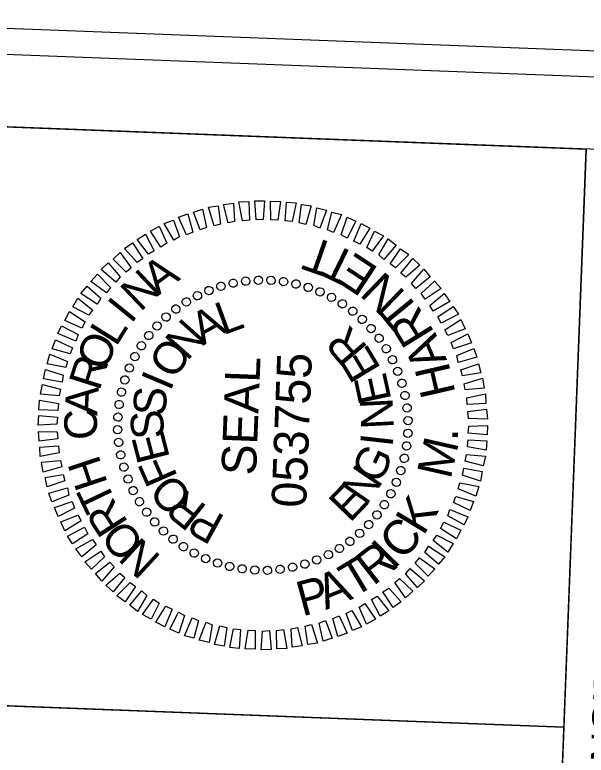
# Model space of a CAD drawing. Extents: x 2097096 to 2098260, y 686401 to 688363.
# Drawn here: x 2097223.6 to 2097322.3, y 688066.3 to 688194.3 of the extents above; entities that cross this region are included whole.
import ezdxf

# ---------------------------------------------------------------- set-up
doc = ezdxf.new("R2010")
doc.units = 0
for name, color, linetype in [('Sheet PE Seal Cell', 7, 'Continuous'), ('Sheet Plot Border Inside CELL', 7, 'Continuous'), ('Sheet Plot Border Outside CELL', 7, 'Continuous'), ('Sheet Profile CELL', 7, 'Continuous'), ('Sheet Sticker Exception Certification CELL', 7, 'Continuous')]:
    doc.layers.add(name, color=color, linetype=linetype)

msp = doc.modelspace()

# ---------------------------------------------------------------- linework, layer by layer
at = {"layer": 'Sheet PE Seal Cell'}
for p, q in [((2097261.29, 688147.95), (2097261.29, 688147.95)), ((2097263.5, 688148.27), (2097263.5, 688148.27)), ((2097265.66, 688148.49), (2097265.66, 688148.49)), ((2097267.86, 688148.45), (2097267.86, 688148.45)), ((2097270.05, 688148.22), (2097270.05, 688148.22)), ((2097272.19, 688147.78), (2097272.19, 688147.78)), ((2097257.13, 688146.71), (2097257.13, 688146.71)), ((2097259.16, 688147.43), (2097259.16, 688147.43)), ((2097274.27, 688147.25), (2097274.27, 688147.25)), ((2097276.34, 688146.47), (2097276.34, 688146.47)), ((2097255.15, 688145.79), (2097255.15, 688145.79)), ((2097278.3, 688145.5), (2097278.3, 688145.5)), ((2097253.21, 688144.71), (2097253.21, 688144.71)), ((2097280.21, 688144.42), (2097280.21, 688144.42)), ((2097251.41, 688143.53), (2097251.41, 688143.53)), ((2097281.96, 688143.11), (2097281.96, 688143.11)), ((2097249.7, 688142.09), (2097249.7, 688142.09)), ((2097283.66, 688141.69), (2097283.66, 688141.69)), ((2097248.14, 688140.6), (2097248.14, 688140.6)), ((2097285.15, 688140.13), (2097285.15, 688140.13)), ((2097246.73, 688138.9), (2097246.73, 688138.9)), ((2097286.59, 688138.43), (2097286.59, 688138.43)), ((2097245.41, 688137.15), (2097245.41, 688137.15)), ((2097287.77, 688136.63), (2097287.77, 688136.63)), ((2097244.34, 688135.24), (2097244.34, 688135.24)), ((2097288.85, 688134.69), (2097288.85, 688134.69)), ((2097243.36, 688133.28), (2097243.36, 688133.28)), ((2097289.77, 688132.7), (2097289.77, 688132.7)), ((2097242.58, 688131.21), (2097242.58, 688131.21)), ((2097290.49, 688130.67), (2097290.49, 688130.67)), ((2097242.05, 688129.13), (2097242.05, 688129.13)), ((2097291.01, 688128.55), (2097291.01, 688128.55)), ((2097241.62, 688126.99), (2097241.62, 688126.99)), ((2097291.33, 688126.34), (2097291.33, 688126.34)), ((2097241.38, 688124.8), (2097241.38, 688124.8)), ((2097266.45, 688123.39), (2097266.45, 688123.39)), ((2097291.55, 688124.18), (2097291.55, 688124.18)), ((2097241.35, 688122.6), (2097241.35, 688122.6)), ((2097291.51, 688121.97), (2097291.51, 688121.97)), ((2097241.57, 688120.44), (2097241.57, 688120.44)), ((2097291.28, 688119.78), (2097291.28, 688119.78)), ((2097241.88, 688118.22), (2097241.88, 688118.22)), ((2097290.85, 688117.65), (2097290.85, 688117.65)), ((2097242.4, 688116.1), (2097242.4, 688116.1)), ((2097290.32, 688115.57), (2097290.32, 688115.57)), ((2097243.12, 688114.07), (2097243.12, 688114.07)), ((2097289.54, 688113.49), (2097289.54, 688113.49)), ((2097244.05, 688112.09), (2097244.05, 688112.09)), ((2097288.56, 688111.53), (2097288.56, 688111.53)), ((2097245.12, 688110.14), (2097245.12, 688110.14)), ((2097287.49, 688109.62), (2097287.49, 688109.62)), ((2097246.31, 688108.35), (2097246.31, 688108.35)), ((2097286.17, 688107.87), (2097286.17, 688107.87)), ((2097247.74, 688106.64), (2097247.74, 688106.64)), ((2097284.75, 688106.17), (2097284.75, 688106.17)), ((2097249.23, 688105.08), (2097249.23, 688105.08)), ((2097283.19, 688104.68), (2097283.19, 688104.68)), ((2097250.93, 688103.67), (2097250.93, 688103.67)), ((2097281.49, 688103.25), (2097281.49, 688103.25)), ((2097252.68, 688102.35), (2097252.68, 688102.35)), ((2097279.69, 688102.06), (2097279.69, 688102.06)), ((2097254.59, 688101.27), (2097254.59, 688101.27)), ((2097277.75, 688100.99), (2097277.75, 688100.99)), ((2097256.56, 688100.3), (2097256.56, 688100.3)), ((2097258.63, 688099.52), (2097258.63, 688099.52)), ((2097273.73, 688099.34), (2097273.73, 688099.34)), ((2097275.76, 688100.06), (2097275.76, 688100.06)), ((2097260.71, 688098.99), (2097260.71, 688098.99)), ((2097262.84, 688098.56), (2097262.84, 688098.56)), ((2097265.04, 688098.32), (2097265.04, 688098.32)), ((2097267.24, 688098.29), (2097267.24, 688098.29)), ((2097269.4, 688098.51), (2097269.4, 688098.51)), ((2097271.61, 688098.82), (2097271.61, 688098.82))]:
    msp.add_line(p, q, dxfattribs=at)
for points in [[(2097260.48, 688158.34), (2097259.65, 688161.52), (2097261.36, 688161.76), (2097261.54, 688158.6)], [(2097262.9, 688158.7), (2097262.32, 688161.97), (2097264.03, 688162.06), (2097264.11, 688158.85)], [(2097265.31, 688158.91), (2097265.03, 688162.17), (2097266.74, 688162.2), (2097266.51, 688158.96)], [(2097267.81, 688158.86), (2097267.78, 688162.11), (2097269.48, 688162.05), (2097269.01, 688158.81)], [(2097270.3, 688158.71), (2097270.53, 688161.96), (2097272.17, 688161.8), (2097271.5, 688158.57)], [(2097255.63, 688157.13), (2097254.45, 688160.22), (2097256.02, 688160.71), (2097256.7, 688157.59)], [(2097258.06, 688157.83), (2097257.04, 688161.07), (2097258.7, 688161.31), (2097259.12, 688158.14)], [(2097272.69, 688158.37), (2097273.12, 688161.56), (2097274.81, 688161.29), (2097273.88, 688158.08)], [(2097275.23, 688157.88), (2097275.74, 688160.96), (2097277.43, 688160.54), (2097276.26, 688157.44)], [(2097253.25, 688156.32), (2097251.86, 688159.32), (2097253.49, 688159.91), (2097254.37, 688156.77)], [(2097277.6, 688157.13), (2097278.37, 688160.21), (2097280, 688159.79), (2097278.63, 688156.69)], [(2097279.97, 688156.29), (2097280.99, 688159.36), (2097282.51, 688158.65), (2097281, 688155.7)], [(2097251.06, 688155.4), (2097249.42, 688158.26), (2097251, 688158.85), (2097252.04, 688155.96)], [(2097282.13, 688155.21), (2097283.4, 688158.26), (2097284.92, 688157.45), (2097283.21, 688154.67)], [(2097248.81, 688154.18), (2097247.02, 688156.91), (2097248.55, 688157.8), (2097249.84, 688154.85)], [(2097284.39, 688154.12), (2097285.75, 688156.92), (2097287.27, 688156.11), (2097285.31, 688153.49)], [(2097246.72, 688152.96), (2097244.71, 688155.49), (2097246.2, 688156.39), (2097247.69, 688153.53)], [(2097286.49, 688152.84), (2097288.1, 688155.58), (2097289.46, 688154.53), (2097287.36, 688152.01)], [(2097244.71, 688151.54), (2097242.55, 688153.92), (2097243.94, 688154.92), (2097245.74, 688152.2)], [(2097242.84, 688149.86), (2097240.58, 688152.1), (2097241.82, 688153.25), (2097243.67, 688150.58)], [(2097288.43, 688151.26), (2097290.23, 688153.9), (2097291.65, 688152.89), (2097289.36, 688150.58)], [(2097290.27, 688149.69), (2097292.32, 688152.22), (2097293.58, 688151.07), (2097291.15, 688148.96)], [(2097241.03, 688148.13), (2097238.51, 688150.28), (2097239.75, 688151.43), (2097241.81, 688149.05)], [(2097292.1, 688147.87), (2097294.25, 688150.34), (2097295.35, 688149.05), (2097292.87, 688147.04)], [(2097239.41, 688146.29), (2097236.73, 688148.24), (2097237.88, 688149.5), (2097240.14, 688147.21)], [(2097293.79, 688146.16), (2097296.07, 688148.27), (2097297.23, 688147.02), (2097294.45, 688145.18)], [(2097237.83, 688144.3), (2097235, 688146.16), (2097236.1, 688147.42), (2097238.47, 688145.37)], [(2097236.4, 688142.4), (2097233.61, 688143.86), (2097234.51, 688145.33), (2097237.04, 688143.33)], [(2097295.26, 688144.1), (2097297.74, 688146.15), (2097298.74, 688144.76), (2097295.88, 688143.12)], [(2097296.69, 688142.14), (2097299.31, 688143.89), (2097300.21, 688142.56), (2097297.25, 688141.02)], [(2097235.17, 688140.15), (2097232.27, 688141.51), (2097233.03, 688143.03), (2097235.76, 688141.23)], [(2097297.85, 688139.9), (2097300.62, 688141.64), (2097301.36, 688140.06), (2097298.42, 688138.92)], [(2097234.13, 688137.94), (2097231.03, 688139.21), (2097231.68, 688140.58), (2097234.53, 688139.07)], [(2097298.97, 688137.7), (2097301.83, 688139.19), (2097302.47, 688137.62), (2097299.38, 688136.58)], [(2097233.15, 688135.72), (2097230.08, 688136.59), (2097230.64, 688138.12), (2097233.54, 688136.76)], [(2097299.93, 688135.46), (2097302.88, 688136.65), (2097303.42, 688135.13), (2097300.19, 688134.2)], [(2097232.4, 688133.35), (2097229.18, 688133.97), (2097229.64, 688135.66), (2097232.69, 688134.39)], [(2097300.64, 688132.98), (2097303.68, 688134.02), (2097304.07, 688132.45), (2097300.95, 688131.92)], [(2097231.76, 688130.82), (2097228.58, 688131.39), (2097228.89, 688133.03), (2097231.95, 688132.01)], [(2097301.2, 688130.56), (2097304.39, 688131.49), (2097304.67, 688129.78), (2097301.41, 688129.5)], [(2097231.27, 688128.44), (2097228.03, 688128.76), (2097228.39, 688130.4), (2097231.51, 688129.63)], [(2097301.66, 688128.14), (2097304.88, 688128.82), (2097304.97, 688127.16), (2097301.76, 688126.94)], [(2097231.02, 688125.95), (2097227.77, 688126.07), (2097227.89, 688127.72), (2097231.12, 688127.14)], [(2097301.86, 688125.73), (2097305.08, 688126.16), (2097305.22, 688124.45), (2097301.97, 688124.53)], [(2097230.88, 688123.55), (2097227.62, 688123.42), (2097227.73, 688125.07), (2097230.97, 688124.75)], [(2097231.03, 688121.04), (2097227.81, 688120.62), (2097227.68, 688122.32), (2097230.93, 688122.25)], [(2097302.02, 688123.22), (2097305.27, 688123.35), (2097305.16, 688121.7), (2097301.92, 688122.03)], [(2097301.88, 688120.83), (2097305.12, 688120.7), (2097305.01, 688119.06), (2097301.78, 688119.63)], [(2097231.24, 688118.63), (2097228.01, 688117.96), (2097227.92, 688119.61), (2097231.14, 688119.84)], [(2097301.63, 688118.33), (2097304.87, 688118.01), (2097304.51, 688116.37), (2097301.38, 688117.14)], [(2097231.7, 688116.21), (2097228.51, 688115.28), (2097228.22, 688117), (2097231.49, 688117.27)], [(2097301.14, 688115.95), (2097304.32, 688115.38), (2097304.01, 688113.74), (2097300.94, 688114.76)], [(2097232.25, 688113.79), (2097229.21, 688112.76), (2097228.82, 688114.32), (2097231.95, 688114.85)], [(2097300.49, 688113.42), (2097303.72, 688112.8), (2097303.25, 688111.12), (2097300.2, 688112.38)], [(2097232.96, 688111.31), (2097230.01, 688110.12), (2097229.47, 688111.64), (2097232.71, 688112.57)], [(2097299.75, 688111.05), (2097302.82, 688110.18), (2097302.26, 688108.65), (2097299.36, 688110.02)], [(2097233.93, 688109.07), (2097231.07, 688107.58), (2097230.43, 688109.16), (2097233.52, 688110.19)], [(2097298.76, 688108.84), (2097301.87, 688107.57), (2097301.21, 688106.19), (2097298.37, 688107.7)], [(2097235.04, 688106.88), (2097232.27, 688105.13), (2097231.53, 688106.71), (2097234.48, 688107.85)], [(2097236.21, 688104.63), (2097233.59, 688102.88), (2097232.69, 688104.22), (2097235.65, 688105.75)], [(2097297.73, 688106.63), (2097300.63, 688105.26), (2097299.87, 688103.74), (2097297.14, 688105.55)], [(2097296.49, 688104.37), (2097299.29, 688102.91), (2097298.38, 688101.45), (2097295.85, 688103.44)], [(2097237.63, 688102.68), (2097235.15, 688100.62), (2097234.15, 688102.01), (2097237.02, 688103.65)], [(2097295.07, 688102.47), (2097297.9, 688100.61), (2097296.8, 688099.36), (2097294.43, 688101.4)], [(2097239.1, 688100.62), (2097236.82, 688098.5), (2097235.67, 688099.75), (2097238.44, 688101.59)], [(2097293.49, 688100.48), (2097296.17, 688098.53), (2097295.02, 688097.27), (2097292.75, 688099.56)], [(2097240.79, 688098.9), (2097238.64, 688096.43), (2097237.54, 688097.73), (2097240.02, 688099.73)], [(2097242.62, 688097.08), (2097240.57, 688094.56), (2097239.32, 688095.71), (2097241.75, 688097.81)], [(2097291.87, 688098.64), (2097294.39, 688096.5), (2097293.14, 688095.34), (2097291.08, 688097.72)], [(2097290.05, 688096.91), (2097292.32, 688094.67), (2097291.07, 688093.52), (2097289.22, 688096.19)], [(2097244.46, 688095.51), (2097242.66, 688092.88), (2097241.25, 688093.88), (2097243.54, 688096.19)], [(2097288.18, 688095.23), (2097290.34, 688092.85), (2097288.96, 688091.85), (2097287.16, 688094.57)], [(2097246.4, 688093.93), (2097244.8, 688091.19), (2097243.44, 688092.25), (2097245.54, 688094.77)], [(2097248.51, 688092.65), (2097247.15, 688089.85), (2097245.63, 688090.66), (2097247.58, 688093.29)], [(2097286.18, 688093.81), (2097288.18, 688091.28), (2097286.7, 688090.39), (2097285.21, 688093.25)], [(2097250.77, 688091.56), (2097249.5, 688088.51), (2097247.98, 688089.32), (2097249.69, 688092.11)], [(2097281.83, 688091.37), (2097283.47, 688088.51), (2097281.9, 688087.92), (2097280.86, 688090.81)], [(2097284.08, 688092.59), (2097285.88, 688089.87), (2097284.34, 688088.98), (2097283.05, 688091.93)], [(2097252.93, 688090.48), (2097251.91, 688087.42), (2097250.38, 688088.13), (2097251.9, 688091.07)], [(2097279.65, 688090.46), (2097281.03, 688087.45), (2097279.41, 688086.86), (2097278.53, 688090)], [(2097255.3, 688089.64), (2097254.53, 688086.57), (2097252.89, 688086.98), (2097254.26, 688090.08)], [(2097257.67, 688088.9), (2097257.15, 688085.82), (2097255.47, 688086.23), (2097256.64, 688089.34)], [(2097274.83, 688088.94), (2097275.86, 688085.7), (2097274.2, 688085.46), (2097273.77, 688088.63)], [(2097277.26, 688089.65), (2097278.44, 688086.55), (2097276.87, 688086.06), (2097276.19, 688089.19)], [(2097260.2, 688088.4), (2097259.78, 688085.21), (2097258.09, 688085.48), (2097259.01, 688088.7)], [(2097262.59, 688088.06), (2097262.37, 688084.81), (2097260.72, 688084.98), (2097261.4, 688088.2)], [(2097265.09, 688087.91), (2097265.11, 688084.66), (2097263.41, 688084.72), (2097263.89, 688087.96)], [(2097267.59, 688087.87), (2097267.86, 688084.6), (2097266.16, 688084.57), (2097266.38, 688087.81)], [(2097270, 688088.07), (2097270.57, 688084.8), (2097268.87, 688084.72), (2097268.79, 688087.92)], [(2097272.41, 688088.43), (2097273.24, 688085.25), (2097271.53, 688085.01), (2097271.35, 688088.17)]]:
    msp.add_lwpolyline(points, close=True, dxfattribs=at)
for centre, major_axis in [((2097263.48, 688148.29), (-0.085, 0.715)), ((2097265.66, 688148.45), (-0.023, 0.72)), ((2097267.85, 688148.43), (0.04, 0.719)), ((2097270.02, 688148.21), (0.103, 0.713)), ((2097259.2, 688147.4), (-0.208, 0.689)), ((2097261.32, 688147.94), (-0.147, 0.705)), ((2097272.17, 688147.8), (0.164, 0.701)), ((2097274.28, 688147.21), (0.225, 0.684)), ((2097255.14, 688145.77), (-0.325, 0.643)), ((2097257.13, 688146.67), (-0.267, 0.668)), ((2097276.33, 688146.44), (0.284, 0.662)), ((2097253.23, 688144.7), (-0.379, 0.612)), ((2097278.3, 688145.49), (0.34, 0.635)), ((2097280.18, 688144.37), (0.394, 0.602)), ((2097251.42, 688143.47), (-0.431, 0.576)), ((2097281.96, 688143.1), (0.445, 0.566)), ((2097249.73, 688142.08), (-0.48, 0.537)), ((2097248.16, 688140.55), (-0.525, 0.493)), ((2097283.61, 688141.67), (0.493, 0.525)), ((2097285.14, 688140.1), (0.537, 0.48)), ((2097246.74, 688138.89), (-0.566, 0.445)), ((2097286.53, 688138.41), (0.576, 0.431)), ((2097245.46, 688137.12), (-0.602, 0.394)), ((2097287.76, 688136.6), (0.612, 0.379)), ((2097244.34, 688135.24), (-0.635, 0.34)), ((2097288.83, 688134.7), (0.643, 0.325)), ((2097243.4, 688133.27), (-0.662, 0.284)), ((2097289.73, 688132.7), (0.668, 0.267)), ((2097242.62, 688131.22), (-0.684, 0.225)), ((2097290.46, 688130.64), (0.689, 0.208)), ((2097242.03, 688129.11), (-0.701, 0.164)), ((2097291, 688128.52), (0.705, 0.147)), ((2097241.62, 688126.96), (-0.713, 0.103)), ((2097291.35, 688126.36), (0.715, 0.085)), ((2097241.41, 688124.78), (-0.719, 0.04)), ((2097291.52, 688124.18), (0.72, 0.023)), ((2097241.38, 688122.6), (-0.72, -0.023)), ((2097291.49, 688121.99), (0.719, -0.04)), ((2097241.54, 688120.42), (-0.715, -0.085)), ((2097291.27, 688119.81), (0.713, -0.103)), ((2097241.9, 688118.26), (-0.705, -0.147)), ((2097290.87, 688117.66), (0.701, -0.164)), ((2097242.44, 688116.14), (-0.689, -0.208)), ((2097290.27, 688115.55), (0.684, -0.225)), ((2097243.16, 688114.07), (-0.668, -0.267)), ((2097289.5, 688113.51), (0.662, -0.284)), ((2097244.06, 688112.08), (-0.643, -0.325)), ((2097288.55, 688111.54), (0.635, -0.34)), ((2097245.13, 688110.17), (-0.612, -0.379)), ((2097287.43, 688109.65), (0.602, -0.394)), ((2097246.37, 688108.36), (-0.576, -0.431)), ((2097286.16, 688107.88), (0.566, -0.445)), ((2097247.75, 688106.67), (-0.537, -0.48)), ((2097284.73, 688106.22), (0.525, -0.493)), ((2097249.28, 688105.1), (-0.493, -0.525)), ((2097283.17, 688104.69), (0.48, -0.537)), ((2097250.94, 688103.68), (-0.445, -0.566)), ((2097252.72, 688102.4), (-0.394, -0.602)), ((2097279.67, 688102.07), (0.379, -0.612)), ((2097281.47, 688103.31), (0.431, -0.576)), ((2097254.6, 688101.28), (-0.34, -0.635)), ((2097277.76, 688101), (0.325, -0.643)), ((2097256.57, 688100.33), (-0.284, -0.662)), ((2097258.62, 688099.56), (-0.225, -0.684)), ((2097275.76, 688100.1), (0.267, -0.668)), ((2097260.72, 688098.97), (-0.164, -0.701)), ((2097262.87, 688098.56), (-0.103, -0.713)), ((2097265.05, 688098.35), (-0.04, -0.719)), ((2097267.24, 688098.32), (0.023, -0.72)), ((2097269.42, 688098.48), (0.085, -0.715)), ((2097271.58, 688098.84), (0.147, -0.705)), ((2097273.7, 688099.38), (0.208, -0.689))]:
    msp.add_ellipse(centre, major_axis=major_axis, ratio=0.999708, dxfattribs=at)
at = {"layer": 'Sheet Plot Border Inside CELL'}
msp.add_lwpolyline([(2098173.22, 686483.26), (2098237.09, 688148.54), (2097182.76, 688188.97), (2097118.9, 686523.7)], close=True, dxfattribs=at)
at = {"layer": 'Sheet Plot Border Outside CELL'}
msp.add_lwpolyline([(2098195.16, 686469.41), (2098259.69, 688152.17), (2097160.5, 688194.33), (2097095.97, 686511.57)], close=True, dxfattribs=at)
at = {"layer": 'Sheet Profile CELL'}
msp.add_line((2097206.03, 688075.5), (2097318.4, 688071.19), dxfattribs=at)
for points in [[(2097184.83, 688176.38), (2097127.35, 686677.48), (2098176.58, 686637.25), (2098234.06, 688136.14)], [(2097206.03, 688075.5), (2097209.86, 688175.42), (2097322.28, 688171.11), (2097318.45, 688071.19)], [(2097202.2, 687975.52), (2097206.03, 688075.5), (2097318.45, 688071.19), (2097314.61, 687971.21)]]:
    msp.add_lwpolyline(points, close=True, dxfattribs=at)
at = {"layer": 'Sheet Sticker Exception Certification CELL'}
msp.add_line((2097314.61, 687971.21), (2097322.28, 688171.1), dxfattribs=at)

# ---------------------------------------------------------------- texts
at = {"layer": 'Sheet PE Seal Cell'}
for s, height, rotation, p in [('T', 6, 160.7594, (2097279.53, 688154.52)), ('T', 6, 153.9592, (2097283.12, 688152.75)), ('E', 6, 146.8498, (2097286.63, 688150.46)), ('A', 5.64, 36.4209, (2097248.34, 688145.7)), ('N', 5.64, 43.6226, (2097245.28, 688142.86)), ('N', 6, 136.124, (2097291.31, 688146.23)), ('I', 5.64, 50.8238, (2097243.65, 688140.77)), ('T', 6, 129.3238, (2097293.84, 688143.13)), ('L', 5.64, 20.2045, (2097259.59, 688138.91)), ('R', 6, 121.8435, (2097296.18, 688139.39)), ('A', 5.64, 29.564, (2097256.07, 688137.09)), ('N', 5.64, 48.2803, (2097253.36, 688134.35)), ('L', 5.64, 58.0246, (2097241.09, 688136.82)), ('R', 5.64, 130.2851, (2097284.72, 688136.8)), ('O', 5.64, 65.2249, (2097239.08, 688132.49)), ('A', 6, 113.0032, (2097298.29, 688134.63)), ('O', 5.64, 57.6372, (2097251.23, 688131.08)), ('E', 5.64, 120.9278, (2097286.94, 688133.16)), ('R', 5.64, 72.4248, (2097238.2, 688129.17)), ('SEAL', 5.998, 87.8037, (2097265.26, 688114.63)), ('053755', 5.998, 87.8037, (2097273.91, 688109.05)), ('H', 6, 103.0192, (2097299.75, 688128.94)), ('I', 5.64, 66.9933, (2097250.45, 688129.1)), ('E', 5.64, 102.2155, (2097288.68, 688127.79)), ('A', 5.64, 86.824, (2097237.84, 688124.98)), ('S', 5.64, 85.7041, (2097249.59, 688124.83)), ('N', 5.64, 92.8601, (2097289.09, 688122.82)), ('C', 5.64, 94.0236, (2097237.99, 688121.03)), ('S', 5.64, 95.0593, (2097249.5, 688121.23)), ('E', 5.64, 104.4148, (2097250.42, 688117.75)), ('.', 6, 88.7851, (2097300.1, 688120.58)), ('I', 5.64, 83.5049, (2097288.81, 688119.48)), ('M', 6, 77.2556, (2097298.86, 688113.91)), ('G', 5.64, 64.7939, (2097286.66, 688113)), ('H', 5.64, 108.4232, (2097239.69, 688113.35)), ('F', 5.64, 113.7707, (2097251.8, 688114.49)), ('N', 5.64, 55.4377, (2097284.27, 688109.29)), ('O', 5.64, 132.4849, (2097254.62, 688111.08)), ('E', 5.64, 46.0806, (2097281.46, 688106.4)), ('T', 5.64, 115.6235, (2097241.22, 688110.04)), ('R', 5.64, 141.8433, (2097257, 688109.24)), ('R', 5.64, 122.8242, (2097243.29, 688106.56)), ('K', 6, 58.7713, (2097294.18, 688104.13)), ('P', 5.64, 151.2026, (2097260.13, 688107.52)), ('C', 6, 49.1892, (2097290.59, 688099.78)), ('O', 5.64, 130.0254, (2097246.25, 688103)), ('N', 5.64, 137.2272, (2097249.06, 688100.59)), ('I', 6, 45.3872, (2097288.97, 688098.23)), ('R', 6, 37.907, (2097285.5, 688095.51)), ('T', 6, 31.1067, (2097282.07, 688093.45)), ('A', 6, 22.2664, (2097277.28, 688091.41)), ('P', 6, 15.1571, (2097273.24, 688090.31))]:
    msp.add_text(s, height=height, rotation=rotation, dxfattribs=at).set_placement(p)
at = {"layer": 'Sheet Sticker Exception Certification CELL'}
msp.add_text('DOCUMENT NOT CONSIDERED FINAL', height=5.5, rotation=87.8037, dxfattribs=at).set_placement((2097325.76, 687991.87))

doc.saveas('drawing.dxf')
